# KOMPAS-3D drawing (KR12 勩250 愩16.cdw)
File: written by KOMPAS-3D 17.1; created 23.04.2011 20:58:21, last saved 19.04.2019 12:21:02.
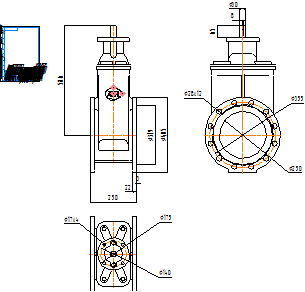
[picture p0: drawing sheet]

Sheet 1: A4, portrait

Title block, sheet 1: name: KR12 Ду250 Ру16; material: Внимание! Данный продукт является объектом авторского права ООО «Торговый Дом АДЛ». / Запрещается изменение, копирование, распространение / (в том числе путем копирования на другие сайты и ресурсы в Интернете) / или любое иное использование информации и объектов без предварительного / согласия правообладателя (ООО «Торговый Дом АДЛ»).; scale: 1:1; sheets: 1; organisation: ООО "Торговый дом АДЛ"; sheet format: A4; stored path: \\adlc.lan\data\АДЛ_ПКД\3D-модели\ADL production\Клиновые задвижки серии KR ГРАНАР\Клиновые задвижки KR12\KOMPAS 2D\KR12 Ду250 Ру16.cdw

Views: Спереди 4, Проекционный вид 5, Проекционный вид 6
Dimensions and other numbers on the sheet: 250; 22; 3; 405; 319; 586; 17; 175; 140; 355; 28; 65; 30; 8; 1:1; 1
